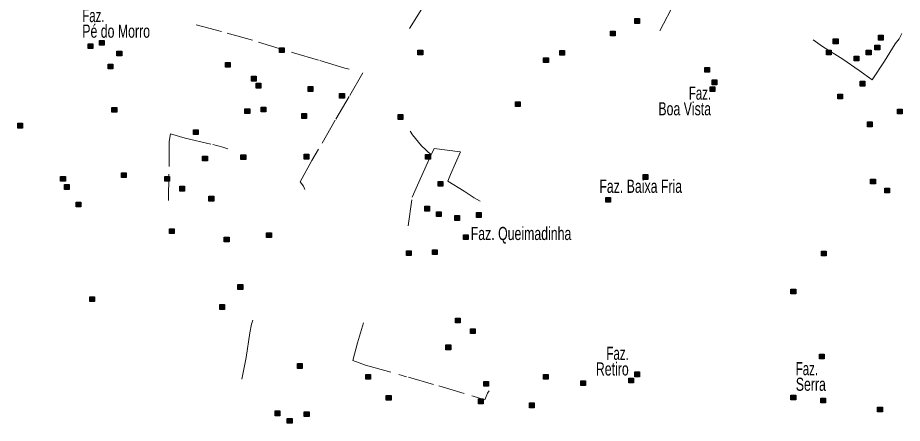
# Model space of a CAD drawing. Extents: x 445.6 to 500, y 8618.1 to 8673.4.
# Drawn here: x 473.24 to 484, y 8653.88 to 8658.81 of the extents above; entities that cross this region are included whole.
import ezdxf
from ezdxf.enums import TextEntityAlignment as Align

# ---------------------------------------------------------------- set-up
doc = ezdxf.new("R2010")
doc.units = 0
doc.header["$LTSCALE"] = 0.064
doc.linetypes.add('DOT_DASHED', pattern=[7.7, 5, -1.2, 0.3, -1.2])
doc.layers.add('2', color=7, linetype='Continuous', lineweight=25)
doc.layers.add('22', color=7, linetype='DOT_DASHED', lineweight=13)
doc.layers.add('61', color=7, linetype='Continuous')

msp = doc.modelspace()

# ---------------------------------------------------------------- hatches: boundary and pattern name
at = {"layer": '2'}
for points in [[(480.7475, 8658.7999), (480.8055, 8658.7999), (480.8055, 8658.7419), (480.7475, 8658.7419)], [(480.4503, 8658.6475), (480.5083, 8658.6475), (480.5083, 8658.5895), (480.4503, 8658.5895)], [(483.7129, 8658.5971), (483.7709, 8658.5971), (483.7709, 8658.5391), (483.7129, 8658.5391)], [(474.0959, 8658.4943), (474.1539, 8658.4943), (474.1539, 8658.4363), (474.0959, 8658.4363)], [(474.234, 8658.536), (474.292, 8658.536), (474.292, 8658.478), (474.234, 8658.478)], [(483.1622, 8658.5527), (483.2202, 8658.5527), (483.2202, 8658.4947), (483.1622, 8658.4947)], [(483.669, 8658.4785), (483.727, 8658.4785), (483.727, 8658.4205), (483.669, 8658.4205)], [(474.4468, 8658.4039), (474.5048, 8658.4039), (474.5048, 8658.3459), (474.4468, 8658.3459)], [(476.4247, 8658.4445), (476.4827, 8658.4445), (476.4827, 8658.3865), (476.4247, 8658.3865)], [(478.1087, 8658.4174), (478.1667, 8658.4174), (478.1667, 8658.3594), (478.1087, 8658.3594)], [(479.8332, 8658.414), (479.8912, 8658.414), (479.8912, 8658.356), (479.8332, 8658.356)], [(483.0779, 8658.4175), (483.1359, 8658.4175), (483.1359, 8658.3595), (483.0779, 8658.3595)], [(483.5643, 8658.4175), (483.6223, 8658.4175), (483.6223, 8658.3595), (483.5643, 8658.3595)], [(474.3387, 8658.248), (474.3967, 8658.248), (474.3967, 8658.19), (474.3387, 8658.19)], [(475.7673, 8658.2683), (475.8253, 8658.2683), (475.8253, 8658.2103), (475.7673, 8658.2103)], [(479.6373, 8658.3226), (479.6953, 8658.3226), (479.6953, 8658.2646), (479.6373, 8658.2646)], [(483.4172, 8658.3431), (483.4752, 8658.3431), (483.4752, 8658.2851), (483.4172, 8658.2851)], [(481.5975, 8658.2067), (481.6555, 8658.2067), (481.6555, 8658.1487), (481.5975, 8658.1487)], [(476.082, 8658.0984), (476.14, 8658.0984), (476.14, 8658.0404), (476.082, 8658.0404)], [(481.6887, 8658.0542), (481.7467, 8658.0542), (481.7467, 8657.9962), (481.6887, 8657.9962)], [(483.4895, 8658.0375), (483.5475, 8658.0375), (483.5475, 8657.9795), (483.4895, 8657.9795)], [(476.1394, 8658.0137), (476.1974, 8658.0137), (476.1974, 8657.9557), (476.1394, 8657.9557)], [(476.771, 8657.9731), (476.829, 8657.9731), (476.829, 8657.9151), (476.771, 8657.9151)], [(481.6651, 8657.9695), (481.7231, 8657.9695), (481.7231, 8657.9115), (481.6651, 8657.9115)], [(477.1561, 8657.8884), (477.2141, 8657.8884), (477.2141, 8657.8304), (477.1561, 8657.8304)], [(483.2159, 8657.8816), (483.2739, 8657.8816), (483.2739, 8657.8236), (483.2159, 8657.8236)], [(474.3851, 8657.7192), (474.4431, 8657.7192), (474.4431, 8657.6612), (474.3851, 8657.6612)], [(476.0043, 8657.702), (476.0623, 8657.702), (476.0623, 8657.644), (476.0043, 8657.644)], [(476.2002, 8657.7224), (476.2582, 8657.7224), (476.2582, 8657.6644), (476.2002, 8657.6644)], [(479.296, 8657.7869), (479.354, 8657.7869), (479.354, 8657.7289), (479.296, 8657.7289)], [(476.6967, 8657.6444), (476.7547, 8657.6444), (476.7547, 8657.5864), (476.6967, 8657.5864)], [(477.8672, 8657.6315), (477.9252, 8657.6315), (477.9252, 8657.5735), (477.8672, 8657.5735)], [(483.9442, 8657.6992), (484.0022, 8657.6992), (484.0022, 8657.6412), (483.9442, 8657.6412)], [(473.2386, 8657.526), (473.2966, 8657.526), (473.2966, 8657.468), (473.2386, 8657.468)], [(483.5794, 8657.5433), (483.6374, 8657.5433), (483.6374, 8657.4853), (483.5794, 8657.4853)], [(475.3769, 8657.4482), (475.4349, 8657.4482), (475.4349, 8657.3902), (475.3769, 8657.3902)], [(475.4884, 8657.1263), (475.5464, 8657.1263), (475.5464, 8657.0683), (475.4884, 8657.0683)], [(475.9551, 8657.1444), (476.0131, 8657.1444), (476.0131, 8657.0864), (475.9551, 8657.0864)], [(476.7237, 8657.1498), (476.7817, 8657.1498), (476.7817, 8657.0918), (476.7237, 8657.0918)], [(478.2016, 8657.1481), (478.2596, 8657.1481), (478.2596, 8657.0901), (478.2016, 8657.0901)], [(473.7603, 8656.8789), (473.8183, 8656.8789), (473.8183, 8656.8209), (473.7603, 8656.8209)], [(474.5001, 8656.923), (474.5581, 8656.923), (474.5581, 8656.865), (474.5001, 8656.865)], [(475.0274, 8656.8809), (475.0854, 8656.8809), (475.0854, 8656.8229), (475.0274, 8656.8229)], [(480.8476, 8656.9023), (480.9056, 8656.9023), (480.9056, 8656.8443), (480.8476, 8656.8443)], [(483.6166, 8656.8465), (483.6746, 8656.8465), (483.6746, 8656.7885), (483.6166, 8656.7885)], [(473.8076, 8656.7807), (473.8656, 8656.7807), (473.8656, 8656.7227), (473.8076, 8656.7227)], [(475.2114, 8656.7604), (475.2694, 8656.7604), (475.2694, 8656.7024), (475.2114, 8656.7024)], [(478.3536, 8656.8195), (478.4116, 8656.8195), (478.4116, 8656.7615), (478.3536, 8656.7615)], [(483.7889, 8656.7381), (483.8469, 8656.7381), (483.8469, 8656.6801), (483.7889, 8656.6801)], [(475.5661, 8656.6384), (475.6241, 8656.6384), (475.6241, 8656.5804), (475.5661, 8656.5804)], [(473.9495, 8656.5672), (474.0075, 8656.5672), (474.0075, 8656.5092), (473.9495, 8656.5092)], [(480.395, 8656.6251), (480.453, 8656.6251), (480.453, 8656.5671), (480.395, 8656.5671)], [(478.1931, 8656.5166), (478.2511, 8656.5166), (478.2511, 8656.4586), (478.1931, 8656.4586)], [(478.3333, 8656.4502), (478.3913, 8656.4502), (478.3913, 8656.3922), (478.3333, 8656.3922)], [(478.8197, 8656.44), (478.8777, 8656.44), (478.8777, 8656.382), (478.8197, 8656.382)], [(478.5563, 8656.4028), (478.6143, 8656.4028), (478.6143, 8656.3448), (478.5563, 8656.3448)], [(475.0864, 8656.242), (475.1444, 8656.242), (475.1444, 8656.184), (475.0864, 8656.184)], [(475.7518, 8656.1404), (475.8098, 8656.1404), (475.8098, 8656.0824), (475.7518, 8656.0824)], [(476.2677, 8656.1947), (476.3257, 8656.1947), (476.3257, 8656.1367), (476.2677, 8656.1367)], [(478.661, 8656.169), (478.719, 8656.169), (478.719, 8656.111), (478.661, 8656.111)], [(478.2841, 8655.9876), (478.3421, 8655.9876), (478.3421, 8655.9296), (478.2841, 8655.9296)], [(477.9702, 8655.9745), (478.0282, 8655.9745), (478.0282, 8655.9165), (477.9702, 8655.9165)], [(483.0188, 8655.9706), (483.0768, 8655.9706), (483.0768, 8655.9126), (483.0188, 8655.9126)], [(475.9192, 8655.5629), (475.9772, 8655.5629), (475.9772, 8655.5049), (475.9192, 8655.5049)], [(482.6473, 8655.5098), (482.7053, 8655.5098), (482.7053, 8655.4518), (482.6473, 8655.4518)], [(474.1145, 8655.415), (474.1725, 8655.415), (474.1725, 8655.357), (474.1145, 8655.357)], [(475.6975, 8655.32), (475.7555, 8655.32), (475.7555, 8655.262), (475.6975, 8655.262)], [(478.5644, 8655.1541), (478.6224, 8655.1541), (478.6224, 8655.0961), (478.5644, 8655.0961)], [(478.7468, 8655.0254), (478.8048, 8655.0254), (478.8048, 8654.9674), (478.7468, 8654.9674)], [(478.4496, 8654.8289), (478.5076, 8654.8289), (478.5076, 8654.7709), (478.4496, 8654.7709)], [(482.9952, 8654.717), (483.0532, 8654.717), (483.0532, 8654.659), (482.9952, 8654.659)], [(476.6423, 8654.6016), (476.7003, 8654.6016), (476.7003, 8654.5436), (476.6423, 8654.5436)], [(480.7481, 8654.5002), (480.8061, 8654.5002), (480.8061, 8654.4422), (480.7481, 8654.4422)], [(477.4734, 8654.469), (477.5314, 8654.469), (477.5314, 8654.411), (477.4734, 8654.411)], [(478.909, 8654.385), (478.967, 8654.385), (478.967, 8654.327), (478.909, 8654.327)], [(479.6368, 8654.4697), (479.6948, 8654.4697), (479.6948, 8654.4117), (479.6368, 8654.4117)], [(480.0894, 8654.3918), (480.1474, 8654.3918), (480.1474, 8654.3338), (480.0894, 8654.3338)], [(480.6738, 8654.4257), (480.7318, 8654.4257), (480.7318, 8654.3677), (480.6738, 8654.3677)], [(477.7234, 8654.2149), (477.7814, 8654.2149), (477.7814, 8654.1569), (477.7234, 8654.1569)], [(478.8448, 8654.1716), (478.9028, 8654.1716), (478.9028, 8654.1136), (478.8448, 8654.1136)], [(482.6477, 8654.2186), (482.7057, 8654.2186), (482.7057, 8654.1606), (482.6477, 8654.1606)], [(483.0113, 8654.1815), (483.0693, 8654.1815), (483.0693, 8654.1235), (483.0113, 8654.1235)], [(479.4661, 8654.1225), (479.5241, 8654.1225), (479.5241, 8654.0645), (479.4661, 8654.0645)], [(483.7017, 8654.0733), (483.7597, 8654.0733), (483.7597, 8654.0153), (483.7017, 8654.0153)], [(476.3717, 8654.0256), (476.4297, 8654.0256), (476.4297, 8653.9676), (476.3717, 8653.9676)], [(476.7263, 8654.0154), (476.7843, 8654.0154), (476.7843, 8653.9574), (476.7263, 8653.9574)], [(476.5183, 8653.9333), (476.5763, 8653.9333), (476.5763, 8653.8753), (476.5183, 8653.8753)]]:
    msp.add_hatch(color=256, dxfattribs=at).paths.add_polyline_path(points)

# ---------------------------------------------------------------- linework, layer by layer
for points in [[(480.7475, 8658.7999), (480.8055, 8658.7999), (480.8055, 8658.7419), (480.7475, 8658.7419)], [(480.4503, 8658.6475), (480.5083, 8658.6475), (480.5083, 8658.5895), (480.4503, 8658.5895)], [(483.7129, 8658.5971), (483.7709, 8658.5971), (483.7709, 8658.5391), (483.7129, 8658.5391)], [(474.0959, 8658.4943), (474.1539, 8658.4943), (474.1539, 8658.4363), (474.0959, 8658.4363)], [(474.234, 8658.536), (474.292, 8658.536), (474.292, 8658.478), (474.234, 8658.478)], [(483.1622, 8658.5527), (483.2202, 8658.5527), (483.2202, 8658.4947), (483.1622, 8658.4947)], [(483.669, 8658.4785), (483.727, 8658.4785), (483.727, 8658.4205), (483.669, 8658.4205)], [(474.4468, 8658.4039), (474.5048, 8658.4039), (474.5048, 8658.3459), (474.4468, 8658.3459)], [(476.4247, 8658.4445), (476.4827, 8658.4445), (476.4827, 8658.3865), (476.4247, 8658.3865)], [(478.1087, 8658.4174), (478.1667, 8658.4174), (478.1667, 8658.3594), (478.1087, 8658.3594)], [(479.8332, 8658.414), (479.8912, 8658.414), (479.8912, 8658.356), (479.8332, 8658.356)], [(483.0779, 8658.4175), (483.1359, 8658.4175), (483.1359, 8658.3595), (483.0779, 8658.3595)], [(483.5643, 8658.4175), (483.6223, 8658.4175), (483.6223, 8658.3595), (483.5643, 8658.3595)], [(474.3387, 8658.248), (474.3967, 8658.248), (474.3967, 8658.19), (474.3387, 8658.19)], [(475.7673, 8658.2683), (475.8253, 8658.2683), (475.8253, 8658.2103), (475.7673, 8658.2103)], [(479.6373, 8658.3226), (479.6953, 8658.3226), (479.6953, 8658.2646), (479.6373, 8658.2646)], [(483.4172, 8658.3431), (483.4752, 8658.3431), (483.4752, 8658.2851), (483.4172, 8658.2851)], [(481.5975, 8658.2067), (481.6555, 8658.2067), (481.6555, 8658.1487), (481.5975, 8658.1487)], [(476.082, 8658.0984), (476.14, 8658.0984), (476.14, 8658.0404), (476.082, 8658.0404)], [(481.6887, 8658.0542), (481.7467, 8658.0542), (481.7467, 8657.9962), (481.6887, 8657.9962)], [(483.4895, 8658.0375), (483.5475, 8658.0375), (483.5475, 8657.9795), (483.4895, 8657.9795)], [(476.1394, 8658.0137), (476.1974, 8658.0137), (476.1974, 8657.9557), (476.1394, 8657.9557)], [(476.771, 8657.9731), (476.829, 8657.9731), (476.829, 8657.9151), (476.771, 8657.9151)], [(481.6651, 8657.9695), (481.7231, 8657.9695), (481.7231, 8657.9115), (481.6651, 8657.9115)], [(477.1561, 8657.8884), (477.2141, 8657.8884), (477.2141, 8657.8304), (477.1561, 8657.8304)], [(483.2159, 8657.8816), (483.2739, 8657.8816), (483.2739, 8657.8236), (483.2159, 8657.8236)], [(474.3851, 8657.7192), (474.4431, 8657.7192), (474.4431, 8657.6612), (474.3851, 8657.6612)], [(476.0043, 8657.702), (476.0623, 8657.702), (476.0623, 8657.644), (476.0043, 8657.644)], [(476.2002, 8657.7224), (476.2582, 8657.7224), (476.2582, 8657.6644), (476.2002, 8657.6644)], [(479.296, 8657.7869), (479.354, 8657.7869), (479.354, 8657.7289), (479.296, 8657.7289)], [(476.6967, 8657.6444), (476.7547, 8657.6444), (476.7547, 8657.5864), (476.6967, 8657.5864)], [(477.8672, 8657.6315), (477.9252, 8657.6315), (477.9252, 8657.5735), (477.8672, 8657.5735)], [(483.9442, 8657.6992), (484.0022, 8657.6992), (484.0022, 8657.6412), (483.9442, 8657.6412)], [(473.2386, 8657.526), (473.2966, 8657.526), (473.2966, 8657.468), (473.2386, 8657.468)], [(483.5794, 8657.5433), (483.6374, 8657.5433), (483.6374, 8657.4853), (483.5794, 8657.4853)], [(475.3769, 8657.4482), (475.4349, 8657.4482), (475.4349, 8657.3902), (475.3769, 8657.3902)], [(475.4884, 8657.1263), (475.5464, 8657.1263), (475.5464, 8657.0683), (475.4884, 8657.0683)], [(475.9551, 8657.1444), (476.0131, 8657.1444), (476.0131, 8657.0864), (475.9551, 8657.0864)], [(476.7237, 8657.1498), (476.7817, 8657.1498), (476.7817, 8657.0918), (476.7237, 8657.0918)], [(478.2016, 8657.1481), (478.2596, 8657.1481), (478.2596, 8657.0901), (478.2016, 8657.0901)], [(473.7603, 8656.8789), (473.8183, 8656.8789), (473.8183, 8656.8209), (473.7603, 8656.8209)], [(474.5001, 8656.923), (474.5581, 8656.923), (474.5581, 8656.865), (474.5001, 8656.865)], [(475.0274, 8656.8809), (475.0854, 8656.8809), (475.0854, 8656.8229), (475.0274, 8656.8229)], [(480.8476, 8656.9023), (480.9056, 8656.9023), (480.9056, 8656.8443), (480.8476, 8656.8443)], [(483.6166, 8656.8465), (483.6746, 8656.8465), (483.6746, 8656.7885), (483.6166, 8656.7885)], [(473.8076, 8656.7807), (473.8656, 8656.7807), (473.8656, 8656.7227), (473.8076, 8656.7227)], [(475.2114, 8656.7604), (475.2694, 8656.7604), (475.2694, 8656.7024), (475.2114, 8656.7024)], [(478.3536, 8656.8195), (478.4116, 8656.8195), (478.4116, 8656.7615), (478.3536, 8656.7615)], [(483.7889, 8656.7381), (483.8469, 8656.7381), (483.8469, 8656.6801), (483.7889, 8656.6801)], [(475.5661, 8656.6384), (475.6241, 8656.6384), (475.6241, 8656.5804), (475.5661, 8656.5804)], [(473.9495, 8656.5672), (474.0075, 8656.5672), (474.0075, 8656.5092), (473.9495, 8656.5092)], [(480.395, 8656.6251), (480.453, 8656.6251), (480.453, 8656.5671), (480.395, 8656.5671)], [(478.1931, 8656.5166), (478.2511, 8656.5166), (478.2511, 8656.4586), (478.1931, 8656.4586)], [(478.3333, 8656.4502), (478.3913, 8656.4502), (478.3913, 8656.3922), (478.3333, 8656.3922)], [(478.8197, 8656.44), (478.8777, 8656.44), (478.8777, 8656.382), (478.8197, 8656.382)], [(478.5563, 8656.4028), (478.6143, 8656.4028), (478.6143, 8656.3448), (478.5563, 8656.3448)], [(475.0864, 8656.242), (475.1444, 8656.242), (475.1444, 8656.184), (475.0864, 8656.184)], [(475.7518, 8656.1404), (475.8098, 8656.1404), (475.8098, 8656.0824), (475.7518, 8656.0824)], [(476.2677, 8656.1947), (476.3257, 8656.1947), (476.3257, 8656.1367), (476.2677, 8656.1367)], [(478.661, 8656.169), (478.719, 8656.169), (478.719, 8656.111), (478.661, 8656.111)], [(478.2841, 8655.9876), (478.3421, 8655.9876), (478.3421, 8655.9296), (478.2841, 8655.9296)], [(477.9702, 8655.9745), (478.0282, 8655.9745), (478.0282, 8655.9165), (477.9702, 8655.9165)], [(483.0188, 8655.9706), (483.0768, 8655.9706), (483.0768, 8655.9126), (483.0188, 8655.9126)], [(475.9192, 8655.5629), (475.9772, 8655.5629), (475.9772, 8655.5049), (475.9192, 8655.5049)], [(482.6473, 8655.5098), (482.7053, 8655.5098), (482.7053, 8655.4518), (482.6473, 8655.4518)], [(474.1145, 8655.415), (474.1725, 8655.415), (474.1725, 8655.357), (474.1145, 8655.357)], [(475.6975, 8655.32), (475.7555, 8655.32), (475.7555, 8655.262), (475.6975, 8655.262)], [(478.5644, 8655.1541), (478.6224, 8655.1541), (478.6224, 8655.0961), (478.5644, 8655.0961)], [(478.7468, 8655.0254), (478.8048, 8655.0254), (478.8048, 8654.9674), (478.7468, 8654.9674)], [(478.4496, 8654.8289), (478.5076, 8654.8289), (478.5076, 8654.7709), (478.4496, 8654.7709)], [(482.9952, 8654.717), (483.0532, 8654.717), (483.0532, 8654.659), (482.9952, 8654.659)], [(476.6423, 8654.6016), (476.7003, 8654.6016), (476.7003, 8654.5436), (476.6423, 8654.5436)], [(480.7481, 8654.5002), (480.8061, 8654.5002), (480.8061, 8654.4422), (480.7481, 8654.4422)], [(477.4734, 8654.469), (477.5314, 8654.469), (477.5314, 8654.411), (477.4734, 8654.411)], [(478.909, 8654.385), (478.967, 8654.385), (478.967, 8654.327), (478.909, 8654.327)], [(479.6368, 8654.4697), (479.6948, 8654.4697), (479.6948, 8654.4117), (479.6368, 8654.4117)], [(480.0894, 8654.3918), (480.1474, 8654.3918), (480.1474, 8654.3338), (480.0894, 8654.3338)], [(480.6738, 8654.4257), (480.7318, 8654.4257), (480.7318, 8654.3677), (480.6738, 8654.3677)], [(477.7234, 8654.2149), (477.7814, 8654.2149), (477.7814, 8654.1569), (477.7234, 8654.1569)], [(478.8448, 8654.1716), (478.9028, 8654.1716), (478.9028, 8654.1136), (478.8448, 8654.1136)], [(482.6477, 8654.2186), (482.7057, 8654.2186), (482.7057, 8654.1606), (482.6477, 8654.1606)], [(483.0113, 8654.1815), (483.0693, 8654.1815), (483.0693, 8654.1235), (483.0113, 8654.1235)], [(479.4661, 8654.1225), (479.5241, 8654.1225), (479.5241, 8654.0645), (479.4661, 8654.0645)], [(483.7017, 8654.0733), (483.7597, 8654.0733), (483.7597, 8654.0153), (483.7017, 8654.0153)], [(476.3717, 8654.0256), (476.4297, 8654.0256), (476.4297, 8653.9676), (476.3717, 8653.9676)], [(476.7263, 8654.0154), (476.7843, 8654.0154), (476.7843, 8653.9574), (476.7263, 8653.9574)], [(476.5183, 8653.9333), (476.5763, 8653.9333), (476.5763, 8653.8753), (476.5183, 8653.8753)]]:
    msp.add_lwpolyline(points, close=True, dxfattribs=at)
at = {"layer": '22'}
for points in [[(481.8377, 8660.1516), (481.6543, 8659.8071), (481.474, 8659.4563), (481.4212, 8659.3477), (481.1906, 8658.9173), (481.0974, 8658.7372), (481.0539, 8658.6503)], [(478.3826, 8659.2719), (478.1362, 8658.8873), (478.0066, 8658.6797)], [(475.4092, 8658.7262), (475.787, 8658.6248), (476.1673, 8658.5151), (476.5927, 8658.3857), (476.9167, 8658.29), (477.2201, 8658.1957), (477.2709, 8658.1844)], [(482.9158, 8658.5441), (483.0296, 8658.4608), (483.2791, 8658.3068), (483.4754, 8658.1697), (483.6352, 8658.0549), (483.7838, 8658.2844), (483.9155, 8658.4944), (483.966, 8658.556), (483.9981, 8658.6207)], [(477.4371, 8658.1423), (477.271, 8657.8524), (477.1012, 8657.5634), (476.9005, 8657.2128), (476.8195, 8657.074), (476.6758, 8656.8132), (476.7144, 8656.7593), (476.7339, 8656.7214)], [(475.0717, 8656.5868), (475.08, 8656.9988), (475.0835, 8657.3058), (475.0975, 8657.3965), (475.2757, 8657.3442), (475.6146, 8657.2674), (475.7334, 8657.236), (475.7955, 8657.2151)], [(478.2693, 8657.1444), (478.151, 8657.2518), (478.0406, 8657.3863), (478.0136, 8657.432)], [(478.2693, 8657.1444), (478.306, 8657.2177), (478.6275, 8657.1797), (478.5048, 8656.905), (478.471, 8656.8205), (478.6699, 8656.7022), (478.7926, 8656.6177), (478.8654, 8656.5777)], [(477.9882, 8656.2772), (478.0394, 8656.6262), (478.1367, 8656.8459), (478.2637, 8657.1332), (478.2693, 8657.1444)], [(475.9678, 8654.4138), (476.0173, 8654.6749), (476.0651, 8654.9757), (476.0834, 8655.082), (476.0978, 8655.1309)], [(477.4479, 8655.0993), (477.3749, 8654.8546), (477.3161, 8654.6381), (477.4705, 8654.5831), (477.9923, 8654.4363), (478.3634, 8654.3299), (478.7802, 8654.2042), (478.9235, 8654.1602), (478.9565, 8654.2409), (478.9736, 8654.2708)]]:
    msp.add_lwpolyline(points, dxfattribs=at)

# ---------------------------------------------------------------- texts
at = {"layer": '61'}
for s, width, p in [('Faz.', 0.65, (474.0245, 8658.7578)), ('Pé do Morro', 0.7, (474.0245, 8658.5678)), ('Faz. Queimadinha', 0.7, (478.7511, 8656.1058)), ('Faz.', 0.65, (482.7061, 8654.4608)), ('Serra', 0.7, (482.7061, 8654.2708))]:
    msp.add_text(s, height=0.16, dxfattribs=dict(at, width=width)).set_placement(p)
for s, width, p in [('Faz.', 0.65, (481.6753, 8657.8135)), ('Boa Vista', 0.7, (481.6753, 8657.6235)), ('Faz.', 0.65, (480.6733, 8654.647)), ('Retiro', 0.7, (480.6733, 8654.457))]:
    msp.add_text(s, height=0.16, dxfattribs=dict(at, width=width)).set_placement(p, align=Align.RIGHT)
at = {"layer": '61', "width": 0.7}
msp.add_text('Faz. Baixa Fria', height=0.16, dxfattribs=at).set_placement((480.8194, 8656.68), align=Align.CENTER)

doc.saveas('drawing.dxf')
